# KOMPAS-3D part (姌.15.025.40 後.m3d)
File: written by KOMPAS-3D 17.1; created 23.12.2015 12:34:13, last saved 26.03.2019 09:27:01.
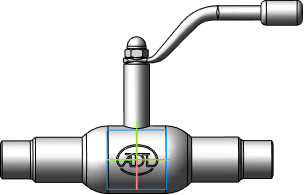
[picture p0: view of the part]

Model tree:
1. Операция без истории:3  (labels: Сталь 20  ГОСТ 1050-88)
